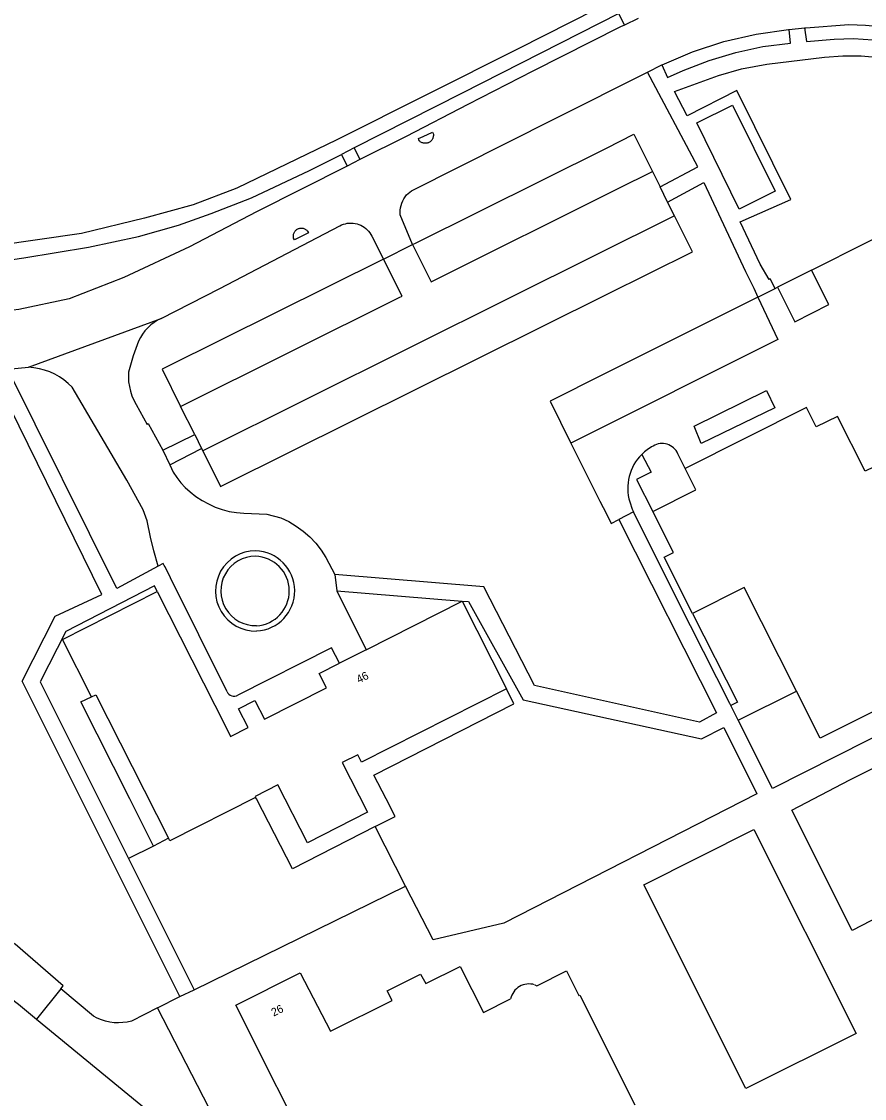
# Model space of a CAD drawing. Extents: x 158132 to 159658, y 385257 to 387209.
# Drawn here: x 158926.9 to 159032.3, y 386462.6 to 386597.1 of the extents above; entities that cross this region are included whole.
import ezdxf

# ---------------------------------------------------------------- set-up
doc = ezdxf.new("R2010")
doc.units = 0
for name, color, linetype in [('IMGEO_Pand', 7, 'Continuous'), ('IMGEO_Pand_nummerreeks', 7, 'Continuous'), ('IMGEO_Parkeervlak_gesloten', 7, 'Continuous'), ('IMGEO_Parkeervlak_open', 7, 'Continuous'), ('IMGEO_Rijbaan_lokaal_gesloten', 7, 'Continuous'), ('IMGEO_Rijbaan_lokaal_open', 7, 'Continuous'), ('IMGEO_Verkeerseiland_open', 7, 'Continuous'), ('IMGEO_Voetpad_open', 7, 'Continuous')]:
    doc.layers.add(name, color=color, linetype=linetype)

msp = doc.modelspace()

# ---------------------------------------------------------------- linework, layer by layer
at = {"layer": 'IMGEO_Pand'}
for points in [[(159021.1, 386575.91), (159016.61, 386573.69), (159011.29, 386584.45), (159015.77, 386586.66), (159021.1, 386575.91)], [(159051.01, 386562.95), (159054.86, 386555.28), (159051.91, 386553.8), (159051.29, 386555.03), (159038.83, 386548.71), (159040.73, 386544.97), (159032.36, 386540.93), (159028.89, 386547.79), (159026.2, 386546.5), (159024.99, 386548.9), (159009.85, 386541.29)], [(159005.81, 386535.92), (159011.17, 386538.61), (159009.85, 386541.29)], [(159010.76, 386523.17), (159007.22, 386530.22), (159008.38, 386530.8), (159005.81, 386535.92)], [(158935.67, 386512.77), (158932.05, 386519.93), (158943.87, 386525.92)], [(158943.87, 386525.92), (158952.52, 386508.85), (158953.04, 386507.82), (158955.22, 386508.93), (158954.04, 386511.26), (158956.08, 386512.29), (158957.26, 386509.97), (158965.01, 386513.89), (158964.11, 386515.67), (158966.63, 386516.95)], [(159023.76, 386513.46), (159017.24, 386526.43), (159010.76, 386523.17)], [(158969.98, 386518.65), (158981.96, 386524.72)], [(158981.96, 386524.72), (158987.51, 386513.77)], [(159045.09, 386517.18), (159043.13, 386519.24), (159040.41, 386518.13), (159041.89, 386515.18), (159026.71, 386507.58), (159023.76, 386513.46)], [(158969.98, 386518.65), (158966.63, 386516.95)], [(158935.67, 386512.77), (158936.18, 386513.03), (158945.27, 386495.1)], [(158987.51, 386513.77), (158969.39, 386504.59), (158968.93, 386505.52), (158966.99, 386504.54), (158970.13, 386498.34), (158962.63, 386494.54), (158958.96, 386501.78), (158956.09, 386500.33), (158956.16, 386500.19)], [(158956.16, 386500.19), (158945.44, 386494.76), (158945.27, 386495.1)], [(158963.99, 386453.77), (158953.68, 386474.23), (158961.72, 386478.28), (158965.53, 386470.98), (158973.22, 386474.82), (158972.61, 386476.05), (158976.77, 386478.13), (158977.42, 386476.94), (158981.74, 386479.08)], [(158981.74, 386479.08), (158984.64, 386473.35), (158988.03, 386475.04)], [(158991.04, 386476.8), (158991.33, 386476.68), (158995.01, 386478.52), (158996.57, 386475.47), (158996.67, 386475.51), (159003.55, 386461.79)]]:
    msp.add_lwpolyline(points, dxfattribs=at)
msp.add_arc((158990.35, 386474.52), 2.38, 73.2469, 167.5544, dxfattribs=at)
at = {"layer": 'IMGEO_Parkeervlak_gesloten'}
for points in [[(159025.65, 386566.07), (159021.39, 386563.93)], [(159021.39, 386563.93), (159023.55, 386559.62), (159027.82, 386561.76), (159025.65, 386566.07)], [(159018.92, 386562.7), (159000, 386553.22), (158999.68, 386553.06), (158992.96, 386549.69), (158995.57, 386544.45)], [(159018.92, 386562.7), (159021.41, 386557.38), (158995.57, 386544.45)], [(159010.96, 386546.57), (159020.03, 386551.03), (159021.04, 386548.87), (159011.83, 386544.41), (159010.96, 386546.57)]]:
    msp.add_lwpolyline(points, dxfattribs=at)
at = {"layer": 'IMGEO_Parkeervlak_open'}
for points in [[(158975.79, 386569.26), (158976.14, 386569.43), (159000, 386581.3), (159003.45, 386583.02), (159005.76, 386578.37)], [(158975.79, 386569.26), (158978.1, 386564.61), (159001.48, 386576.24), (159005.76, 386578.37)], [(159005.76, 386578.37), (159006.71, 386576.47)], [(159025.65, 386566.07), (159032.6, 386569.55), (159044.38, 386575.53), (159044.19, 386575.96), (159050.09, 386578.94), (159053.63, 386578.06), (159054.82, 386578.85)], [(159008.52, 386572.83), (159007.66, 386574.55)], [(159008.52, 386572.83), (158988.19, 386562.72), (158949.55, 386543.5)], [(158949.55, 386543.5), (158951.78, 386539.02), (158952.37, 386539.31), (159000, 386563), (159010.75, 386568.35), (159008.52, 386572.83)], [(158972.13, 386567.44), (158945.07, 386553.98), (158944.48, 386553.69), (158946.79, 386549.04)], [(158946.79, 386549.04), (158974.1, 386562.62), (158974.48, 386562.81), (158972.13, 386567.44)], [(159021.08, 386563.78), (159021.39, 386563.93)], [(158948.55, 386545.52), (158946.79, 386549.04)], [(158949.42, 386543.76), (158949.55, 386543.5)], [(158995.57, 386544.45), (158995.95, 386543.7), (158999.19, 386537.2), (159000, 386535.61), (159000.6, 386534.43), (159001.57, 386534.92)], [(159002.92, 386537.11), (159003.22, 386536.21), (159003.4, 386535.85)]]:
    msp.add_lwpolyline(points, dxfattribs=at)
msp.add_arc((159008.62, 386538.82), 5.95, 134.7711, 196.6614, dxfattribs=at)
at = {"layer": 'IMGEO_Rijbaan_lokaal_gesloten'}
for points in [[(159003.96, 386597.48), (159002.25, 386596.66)], [(159002.25, 386596.66), (159001.76, 386596.43), (158990.82, 386590.92), (158982.67, 386586.75), (158974.99, 386582.77), (158969.21, 386579.86)], [(159006.94, 386591.69), (159006.99, 386591.72), (159010.77, 386593.34), (159014.69, 386594.62), (159018.7, 386595.55), (159022.78, 386596.12), (159022.84, 386596.13)], [(159022.84, 386596.13), (159024.78, 386596.31)], [(159024.78, 386596.31), (159024.92, 386596.33), (159030.29, 386596.74), (159032.37, 386596.65), (159034.65, 386596.46), (159036.92, 386596.06), (159039.13, 386595.45), (159042.61, 386594.15), (159046.74, 386592.18), (159051.31, 386589.44), (159053.19, 386587.78), (159053.68, 386587.27), (159054.12, 386586.72), (159054.52, 386586.13), (159054.86, 386585.51)], [(158975.79, 386569.26), (158974.22, 386572.96), (158974.21, 386573.26), (158974.23, 386573.56), (158974.27, 386573.86), (158974.34, 386574.15), (158974.44, 386574.44), (158974.55, 386574.71), (158974.69, 386574.98), (158974.85, 386575.23), (158975.03, 386575.47), (158975.65, 386575.98), (158993.6, 386585.01), (159005.15, 386590.8)], [(159005.15, 386590.8), (159006.94, 386591.69)], [(158976.51, 386582.49), (158977.1, 386582.75), (158978.27, 386583.28), (158978.38, 386583.03), (158978.38, 386582.95), (158978.38, 386582.86), (158978.37, 386582.77), (158978.36, 386582.68), (158978.33, 386582.6), (158978.3, 386582.52), (158978.27, 386582.44), (158978.22, 386582.36), (158978.17, 386582.29), (158978.11, 386582.22), (158977.98, 386582.1), (158977.91, 386582.05), (158977.83, 386582.01), (158977.76, 386581.97), (158977.67, 386581.94), (158977.59, 386581.92), (158977.5, 386581.91), (158977.41, 386581.9), (158977.33, 386581.9), (158977.24, 386581.9), (158977.15, 386581.92), (158977.07, 386581.94), (158976.98, 386581.97), (158976.9, 386582.01), (158976.83, 386582.05), (158976.75, 386582.1), (158976.68, 386582.15), (158976.62, 386582.22), (158976.51, 386582.49)], [(158969.21, 386579.86), (158967.62, 386579.06)], [(158967.62, 386579.06), (158956.26, 386573.35), (158947.92, 386568.97), (158939.7, 386565.13), (158932.88, 386562.49), (158926.58, 386561.12), (158922.98, 386560.71), (158918.93, 386560.73)], [(158944.36, 386560.03), (158951.69, 386563.77), (158966.69, 386571.59), (158966.91, 386571.7), (158967.14, 386571.79), (158967.38, 386571.86), (158967.62, 386571.91), (158967.87, 386571.93), (158968.11, 386571.94), (158968.36, 386571.93), (158968.61, 386571.89), (158968.85, 386571.84), (158969.08, 386571.76), (158969.31, 386571.66), (158969.53, 386571.55), (158969.74, 386571.42), (158969.93, 386571.27), (158970.11, 386571.1), (158970.28, 386570.92), (158970.43, 386570.72), (158970.57, 386570.52), (158970.68, 386570.3), (158972.13, 386567.44)], [(158960.89, 386570.14), (158960.88, 386570.22), (158960.88, 386570.31), (158960.88, 386570.39), (158960.89, 386570.48), (158960.91, 386570.56), (158960.93, 386570.65), (158960.97, 386570.73), (158961.01, 386570.8), (158961.05, 386570.88), (158961.1, 386570.94), (158961.16, 386571.01), (158961.22, 386571.07), (158961.29, 386571.12), (158961.36, 386571.17), (158961.43, 386571.21), (158961.51, 386571.24), (158961.6, 386571.27), (158961.68, 386571.29), (158961.76, 386571.3), (158961.85, 386571.31), (158961.93, 386571.31), (158962.02, 386571.3), (158962.1, 386571.28), (158962.19, 386571.26), (158962.27, 386571.23), (158962.34, 386571.19), (158962.42, 386571.15), (158962.49, 386571.1), (158962.55, 386571.04), (158962.61, 386570.98), (158962.67, 386570.91), (158962.76, 386570.73), (158961.04, 386569.84), (158960.91, 386570.05), (158960.89, 386570.14)], [(158972.13, 386567.44), (158975.79, 386569.26)], [(158927.78, 386553.93), (158944.36, 386560.03)], [(158944.36, 386560.03), (158943.9, 386559.79), (158943.47, 386559.52), (158943.06, 386559.21), (158942.68, 386558.86), (158942.34, 386558.48), (158942.03, 386558.07), (158941.76, 386557.63), (158941.53, 386557.17), (158940.85, 386555.37), (158940.29, 386553.33), (158940.27, 386552.72), (158940.3, 386552.12), (158940.39, 386551.52), (158940.52, 386550.94), (158940.71, 386550.36), (158940.95, 386549.81), (158941.24, 386549.28), (158942.6, 386546.79), (158942.74, 386546.89), (158944.57, 386543.55)], [(158925.18, 386553.7), (158927.78, 386553.93)], [(158943.98, 386529.1), (158943.44, 386530.98), (158943.04, 386532.69), (158942.62, 386534.74), (158942.1, 386536.11), (158940.08, 386539.82), (158933.23, 386551.43), (158932.74, 386551.91), (158932.21, 386552.34), (158931.65, 386552.72), (158931.06, 386553.06), (158930.44, 386553.34), (158929.8, 386553.57), (158929.14, 386553.75), (158928.46, 386553.87), (158927.78, 386553.93)], [(158944.57, 386543.55), (158945.46, 386541.72)], [(158945.46, 386541.72), (158945.88, 386540.83), (158946.31, 386540.14), (158946.81, 386539.5), (158947.37, 386538.91), (158947.99, 386538.38), (158948.71, 386537.8), (158949.47, 386537.29), (158950.27, 386536.85), (158951.11, 386536.47), (158951.98, 386536.16), (158952.87, 386535.93), (158953.77, 386535.77), (158954.69, 386535.69), (158957.55, 386535.57), (158959.33, 386535.12), (158960.31, 386534.65), (158961.24, 386534.09), (158962.11, 386533.44), (158962.93, 386532.73), (158963.68, 386531.94), (158964.35, 386531.09), (158964.95, 386530.18), (158966.06, 386528.04)], [(158952.59, 386513.4), (158945.51, 386527.64), (158944.85, 386528.98), (158944.75, 386529.17), (158944.6, 386529.4), (158943.98, 386529.1)], [(158966.06, 386528.04), (158966.31, 386526.01)], [(158966.31, 386526.01), (158969.98, 386518.65)], [(158966.63, 386516.95), (158965.64, 386518.87), (158953.94, 386512.96)], [(158931.82, 386476.28), (158932.11, 386476.66), (158926.1, 386481.87), (158923.89, 386483.13), (158923.17, 386483.47), (158922.43, 386483.75), (158921.66, 386483.96), (158920.88, 386484.1), (158920.09, 386484.17), (158919.3, 386484.16), (158918.51, 386484.09), (158917.73, 386483.94), (158916.96, 386483.72), (158916.22, 386483.44), (158890.56, 386470.58)], [(158895.22, 386466.88), (158915.44, 386476.89), (158916.13, 386477.22), (158916.85, 386477.48), (158917.59, 386477.68), (158918.34, 386477.81), (158919.11, 386477.87), (158919.87, 386477.87), (158920.64, 386477.8), (158921.39, 386477.65), (158922.13, 386477.45), (158922.84, 386477.17), (158926.52, 386474.38), (158928.8, 386472.51)], [(158931.82, 386476.28), (158928.8, 386472.51)]]:
    msp.add_lwpolyline(points, dxfattribs=at)
for centre, radius, start, end in [((158956.16, 386525.99), 5.01, 90.0909, 271.4072), ((158956.04, 386525.99), 5.01, 272.7934, 88.7047), ((158953.48, 386513.84), 0.99, 206.5777, 298.01)]:
    msp.add_arc(centre, radius, start, end, dxfattribs=at)
at = {"layer": 'IMGEO_Rijbaan_lokaal_open'}
for points in [[(158943.9, 386473.92), (158940.65, 386472.27), (158940.12, 386472.14), (158939.58, 386472.07), (158939.03, 386472.04), (158938.49, 386472.05), (158937.94, 386472.12), (158937.41, 386472.24), (158936.89, 386472.41), (158936.38, 386472.62), (158935.9, 386472.87), (158931.82, 386476.28)], [(158982.74, 386433.99), (158969.11, 386444.87), (158968.79, 386445.09), (158965.43, 386448.01), (158951.06, 386460.02), (158943.9, 386473.92)], [(158928.8, 386472.51), (158968.14, 386440.2)]]:
    msp.add_lwpolyline(points, dxfattribs=at)
at = {"layer": 'IMGEO_Verkeerseiland_open'}
for centre, start, end in [((158956.16, 386525.99), 90.0426, 271.3838), ((158956.04, 386525.98), 272.8949, 88.5315)]:
    msp.add_arc(centre, 4.34, start, end, dxfattribs=at)
at = {"layer": 'IMGEO_Voetpad_open'}
for points in [[(159006.72, 386603.53), (159001.96, 386600.31), (158988.97, 386593.69), (158966.33, 386582.33), (158953.82, 386576.29), (158948.36, 386574.23), (158942.3, 386572.55), (158934.39, 386570.62), (158913.24, 386567.6), (158895.75, 386588.72)], [(159002.25, 386596.66), (159001.57, 386598.1), (158981.96, 386588.15), (158968.48, 386581.32)], [(159006.94, 386591.69), (159007.66, 386590.13), (159009.59, 386590.98), (159012.83, 386592.25), (159016.16, 386593.24), (159019.56, 386593.97), (159023.01, 386594.42), (159022.84, 386596.13)], [(159024.78, 386596.31), (159025.03, 386594.63), (159028.48, 386594.92), (159030.9, 386594.98), (159033.32, 386594.83), (159035.71, 386594.47), (159038.07, 386593.9), (159040.36, 386593.13), (159042.58, 386592.16), (159044.71, 386591), (159050.19, 386587.39), (159051.65, 386586.21), (159053.63, 386583.89), (159055.32, 386581.82), (159055.67, 386581.25)], [(159021.08, 386563.78), (159020.49, 386564.97), (159020.34, 386564.89), (159019.22, 386566.79), (159016.72, 386572.07), (159023.06, 386574.86), (159016.32, 386588.48), (159010.11, 386585.34), (159008.52, 386588.38), (159014.02, 386590.36), (159016.9, 386591.21), (159020.04, 386591.79), (159027.24, 386592.66), (159029.54, 386592.84), (159031.85, 386592.83), (159034.14, 386592.62)], [(159006.71, 386576.47), (159011.42, 386578.98), (159005.15, 386590.8)], [(158968.48, 386581.32), (158966.89, 386580.51)], [(158968.48, 386581.32), (158969.21, 386579.86)], [(158918.93, 386560.73), (158914.76, 386565.78), (158927.21, 386567.6), (158935.28, 386568.92), (158941.52, 386570.27), (158946.54, 386571.66), (158950.62, 386573.12), (158955.64, 386575.08), (158962.89, 386578.49), (158966.89, 386580.51)], [(158966.89, 386580.51), (158967.62, 386579.06)], [(159007.66, 386574.55), (159012.2, 386577.01), (159017.4, 386565.89), (159018.41, 386563.82), (159018.92, 386562.7)], [(159007.66, 386574.55), (159006.71, 386576.47)], [(159018.92, 386562.7), (159021.08, 386563.78)], [(158946.71, 386475.35), (158927.01, 386514.71), (158931.11, 386522.84), (158936.96, 386525.53), (158923.1, 386553.6)], [(158943.98, 386529.1), (158938.84, 386526.3), (158925.18, 386553.7)], [(158944.57, 386543.55), (158948.55, 386545.52)], [(158948.55, 386545.52), (158949.42, 386543.76)], [(158945.46, 386541.72), (158949.42, 386543.76)], [(159004.43, 386543.04), (159005.6, 386540.82), (159003.75, 386539.89), (159005.81, 386535.92)], [(159009.85, 386541.29), (159008.94, 386543.13)], [(159003.4, 386535.85), (159001.57, 386534.92)], [(159015.55, 386511.68), (159015.43, 386511.92), (159010.5, 386521.63), (159003.69, 386535.24), (159003.4, 386535.85)], [(159001.57, 386534.92), (159013.75, 386510.75), (159011.64, 386509.6), (158991.03, 386514.18), (158984.67, 386526.52), (158966.06, 386528.04)], [(158943.87, 386525.92), (158943.51, 386526.62), (158932.45, 386520.91), (158929.25, 386514.63), (158940.3, 386492.55)], [(158966.31, 386526.01), (158981.96, 386524.72)], [(158981.96, 386524.72), (158982.76, 386524.67), (158989.61, 386512.37), (159011.88, 386507.53), (159014.67, 386508.92), (159018.8, 386500.64), (158987.17, 386484.47), (158978.35, 386482.4), (158974.88, 386489.12)], [(159010.76, 386523.17), (159016.37, 386512.09), (159015.55, 386511.68)], [(159045.09, 386517.18), (159036.68, 386509.35), (159020.76, 386501.3), (159016.48, 386509.83)], [(158943.4, 386494.1), (158940.43, 386500), (158934.32, 386512.12), (158935.67, 386512.77)], [(158971.11, 386496.55), (158973.59, 386497.8), (158972.47, 386500), (158970.95, 386502.99), (158988.43, 386511.87), (158987.51, 386513.77)], [(159016.48, 386509.83), (159023.76, 386513.46)], [(159016.48, 386509.83), (159015.55, 386511.68)], [(159036.52, 386486.58), (159030.7, 386483.57), (159023.17, 386498.62), (159030.44, 386502.38), (159049.94, 386512.15)], [(158971.11, 386496.55), (158960.76, 386491.29), (158956.26, 386500), (158956.16, 386500.19)], [(158974.88, 386489.12), (158971.11, 386496.55)], [(158945.27, 386495.1), (158943.4, 386494.1)], [(159004.67, 386489.27), (159018.42, 386496.19), (159031.22, 386470.71), (159017.44, 386463.82), (159004.67, 386489.27)], [(158943.4, 386494.1), (158940.3, 386492.55)], [(158940.3, 386492.55), (158948.49, 386476.17)], [(158948.49, 386476.17), (158974.88, 386489.12)], [(158946.71, 386475.35), (158948.49, 386476.17)], [(158943.9, 386473.92), (158946.71, 386475.35)]]:
    msp.add_lwpolyline(points, dxfattribs=at)
for centre, radius, start, end in [((159008.65, 386538.78), 6, 117.8289, 134.7277), ((159006.97, 386542.23), 2.17, 24.5457, 121.1941)]:
    msp.add_arc(centre, radius, start, end, dxfattribs=at)

# ---------------------------------------------------------------- texts
at = {"layer": 'IMGEO_Pand_nummerreeks'}
for s, rotation, p in [('46', 26.3045, (158969.06, 386514.42)), ('26', 26.3517, (158958.42, 386472.82))]:
    msp.add_text(s, height=1, rotation=rotation, dxfattribs=at).set_placement(p)

doc.saveas('drawing.dxf')
